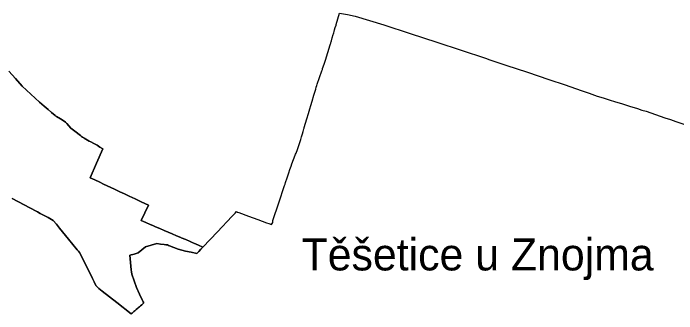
# Model space of a CAD drawing. Extents: x -637420 to -632365, y -1190340 to -1186955.
# Drawn here: x -635803 to -634390, y -1190340 to -1189699 of the extents above; entities that cross this region are included whole.
import ezdxf

# ---------------------------------------------------------------- set-up
doc = ezdxf.new("R2010")
doc.units = 0
for name, color, linetype in [('legenda', 7, 'Continuous'), ('Vrstva 1', 7, 'Continuous'), ('Vrstva 10', 7, 'Continuous'), ('Vrstva 11', 7, 'Continuous')]:
    doc.layers.add(name, color=color, linetype=linetype)

msp = doc.modelspace()

# ---------------------------------------------------------------- linework, layer by layer
at = {"layer": 'Vrstva 1'}
for points in [[(-635491.3, -1190157.8), (-635500.3, -1190153.9), (-635505.9, -1190151.5), (-635511.6, -1190149), (-635521.3, -1190144.8), (-635531, -1190140.6), (-635523.2, -1190124.3), (-635515.3, -1190107.9), (-635523, -1190104.3), (-635530.7, -1190100.7), (-635543.7, -1190094.6), (-635556.8, -1190088.5), (-635566.5, -1190083.9), (-635576.3, -1190079.3), (-635582.2, -1190076.5), (-635588, -1190073.8), (-635595.6, -1190070.3), (-635603.1, -1190066.7), (-635611.2, -1190062.9), (-635619.4, -1190059.1), (-635629.7, -1190054.2), (-635640, -1190049.4), (-635626.4, -1190018.5), (-635612.9, -1189987.6), (-635619, -1189984), (-635625, -1189980.4), (-635631.5, -1189976.8), (-635638, -1189973.2), (-635641.5, -1189971.2), (-635645.1, -1189969.2), (-635648.7, -1189967.2), (-635652.4, -1189965.1), (-635653.4, -1189964.6), (-635654.4, -1189964), (-635656.1, -1189962.7), (-635657.8, -1189961.4), (-635660.4, -1189959.4), (-635663, -1189957.4), (-635669.2, -1189952.6), (-635675.4, -1189947.9), (-635678, -1189945.9), (-635680.6, -1189943.9), (-635685.1, -1189938.7), (-635689.7, -1189933.6), (-635692.2, -1189931.1), (-635694.7, -1189928.6), (-635703.1, -1189923.9), (-635711.5, -1189919.2), (-635712.8, -1189918.1), (-635714.2, -1189916.9), (-635721.7, -1189910.6), (-635729.2, -1189904.2), (-635738, -1189896.8), (-635747.5, -1189888.6), (-635765.9, -1189871.4), (-635784.2, -1189854.1), (-635798.7, -1189838.1), (-635813.2, -1189822.2)], [(-635805.9, -1190093.5), (-635780.4, -1190107.2), (-635755, -1190120.8), (-635753.5, -1190121.6), (-635752, -1190122.4), (-635746.1, -1190125.6), (-635740.2, -1190128.8), (-635729.4, -1190134.6), (-635718.7, -1190140.4), (-635711.7, -1190148.8), (-635704.8, -1190157.3), (-635686, -1190180.2), (-635667.2, -1190203.2), (-635664.7, -1190206.2), (-635662.1, -1190209.3)], [(-635399.4, -1190197.5), (-635409, -1190193.3), (-635418.7, -1190189.1), (-635422.7, -1190187.4), (-635426.7, -1190185.7), (-635436.2, -1190181.6), (-635445.7, -1190177.5), (-635446.7, -1190177.1), (-635455.7, -1190173.2), (-635464.8, -1190169.2), (-635473.5, -1190165.5), (-635482.3, -1190161.7), (-635491.3, -1190157.8)], [(-635525.1, -1190316.4), (-635526.7, -1190313.9), (-635528.2, -1190311.4), (-635534.5, -1190297.6), (-635540.7, -1190283.8), (-635545.7, -1190269.4), (-635550.7, -1190255), (-635551.6, -1190250.5), (-635552.5, -1190245.9), (-635553.2, -1190238.2), (-635553.9, -1190230.4), (-635554.7, -1190222.7), (-635555.4, -1190215), (-635546.2, -1190212.2), (-635537.1, -1190209.4), (-635529.4, -1190203.2), (-635521.7, -1190197), (-635509.8, -1190193.4), (-635497.8, -1190189.9), (-635490.1, -1190190.9), (-635482.3, -1190191.9)], [(-635482.3, -1190191.9), (-635478.5, -1190192.4), (-635474.6, -1190192.9), (-635472.7, -1190193.7), (-635470.8, -1190194.4), (-635461.6, -1190198.2), (-635452.3, -1190201.9), (-635444.4, -1190203.9), (-635436.5, -1190205.9), (-635424.3, -1190208.4), (-635412.1, -1190210.9), (-635410.4, -1190209.1), (-635408.1, -1190206.7), (-635403.7, -1190202.1), (-635399.4, -1190197.5)], [(-635662.1, -1190209.3), (-635648.3, -1190236.8), (-635634.5, -1190264.3), (-635631, -1190271.8), (-635627.4, -1190279.2), (-635620.9, -1190285.4), (-635614.4, -1190291.7), (-635583.2, -1190315.6), (-635552, -1190339.6), (-635550.3, -1190338.1), (-635548.6, -1190336.6), (-635546.7, -1190335), (-635544.8, -1190333.4), (-635541.5, -1190330.6), (-635538.3, -1190327.8), (-635536.4, -1190326.2), (-635534.5, -1190324.5), (-635532.6, -1190322.8), (-635529.9, -1190320.6), (-635528.2, -1190319.1), (-635526.1, -1190317.3), (-635525.1, -1190316.4)]]:
    msp.add_lwpolyline(points, dxfattribs=at)
at = {"layer": 'Vrstva 10'}
for points in [[(-635183.6, -1189942.7), (-635180.7, -1189933.1), (-635177.9, -1189923.6), (-635174.6, -1189912.4), (-635171.7, -1189902.9), (-635169.5, -1189895.5), (-635166.7, -1189885.9), (-635162.9, -1189873.2), (-635159.1, -1189860.5), (-635158, -1189856.7), (-635156.9, -1189853), (-635155.9, -1189850.1), (-635151, -1189835.7), (-635146, -1189821.3), (-635145.5, -1189819.9), (-635145, -1189818.5), (-635144.7, -1189817.5), (-635144.4, -1189816.6), (-635141.2, -1189807.6), (-635138.1, -1189798.6), (-635133.3, -1189782.5), (-635128.5, -1189766.3), (-635127.9, -1189764.3), (-635127.3, -1189762.2), (-635127, -1189761.4), (-635126.4, -1189759.4), (-635125.8, -1189757.4), (-635123.9, -1189750.8), (-635121.9, -1189744.1), (-635121.4, -1189742.4), (-635120.9, -1189740.7), (-635119.9, -1189737.4), (-635118.9, -1189734.1), (-635117.4, -1189729.2), (-635115.9, -1189724.3), (-635115.7, -1189723.4), (-635115.4, -1189722.6), (-635111.9, -1189710.6), (-635108.3, -1189698.7)], [(-635108.3, -1189698.7), (-635091.6, -1189701.7), (-635074.9, -1189704.6), (-635044.6, -1189714), (-635014.4, -1189723.3), (-634957.8, -1189741.9), (-634901.3, -1189760.6), (-634849.6, -1189777.6), (-634797.8, -1189794.7), (-634788.2, -1189797.9), (-634771.1, -1189803.6), (-634754.1, -1189809.2), (-634708.2, -1189824.5), (-634662.4, -1189839.8), (-634628, -1189851.7), (-634593.7, -1189863.5), (-634576.6, -1189869.4), (-634559.6, -1189875.3), (-634546.6, -1189879.3), (-634533.7, -1189883.4), (-634520.7, -1189887.4), (-634507.8, -1189891.5), (-634490.5, -1189896.9), (-634473.3, -1189902.2), (-634464.2, -1189905.1), (-634455.1, -1189907.9), (-634435.2, -1189914.7), (-634415.4, -1189921.5), (-634403.3, -1189925.6), (-634397.5, -1189927.6), (-634391.7, -1189929.6), (-634320.3, -1189953.4)], [(-635813.2, -1189822.2), (-635798.7, -1189838.1), (-635784.2, -1189854.1), (-635765.9, -1189871.4), (-635747.5, -1189888.6), (-635738, -1189896.8), (-635729.2, -1189904.2), (-635721.7, -1189910.6), (-635714.2, -1189916.9), (-635712.8, -1189918.1), (-635711.5, -1189919.2), (-635703.1, -1189923.9), (-635694.7, -1189928.6), (-635692.2, -1189931.1), (-635689.7, -1189933.6), (-635685.1, -1189938.7), (-635680.6, -1189943.9), (-635678, -1189945.9), (-635675.4, -1189947.9), (-635669.2, -1189952.6), (-635663, -1189957.4), (-635660.4, -1189959.4), (-635657.8, -1189961.4), (-635656.1, -1189962.7), (-635654.4, -1189964), (-635653.4, -1189964.6), (-635652.4, -1189965.1), (-635648.7, -1189967.2), (-635645.1, -1189969.2), (-635641.5, -1189971.2), (-635638, -1189973.2), (-635631.5, -1189976.8), (-635625, -1189980.4), (-635619, -1189984), (-635612.9, -1189987.6), (-635626.4, -1190018.5), (-635640, -1190049.4), (-635629.7, -1190054.2), (-635619.4, -1190059.1), (-635611.2, -1190062.9), (-635603.1, -1190066.7), (-635595.6, -1190070.3), (-635588, -1190073.8), (-635582.2, -1190076.5), (-635576.3, -1190079.3), (-635566.5, -1190083.9), (-635556.8, -1190088.5), (-635543.7, -1190094.6), (-635530.7, -1190100.7), (-635523, -1190104.3), (-635515.3, -1190107.9), (-635523.2, -1190124.3), (-635531, -1190140.6), (-635521.3, -1190144.8), (-635511.6, -1190149), (-635505.9, -1190151.5), (-635500.3, -1190153.9), (-635491.3, -1190157.8)], [(-635399.4, -1190197.5), (-635368.7, -1190165), (-635338, -1190132.5), (-635336.2, -1190130.6), (-635334.3, -1190128.6), (-635331.1, -1190125.2), (-635327.9, -1190121.8), (-635325.6, -1190122.7), (-635323.2, -1190123.6), (-635322.8, -1190123.7), (-635302.5, -1190131.2), (-635282.3, -1190138.7), (-635273.3, -1190142), (-635264.2, -1190145.4), (-635258.8, -1190147.4), (-635253.3, -1190149.4), (-635251.8, -1190147.2), (-635250.2, -1190145), (-635250.2, -1190145), (-635250.3, -1190142.8), (-635250.4, -1190140.7), (-635237.9, -1190103.4), (-635225.4, -1190066.2), (-635224.4, -1190063.1), (-635223.3, -1190059.9), (-635219.9, -1190049.5), (-635216.4, -1190039.1), (-635214, -1190031.9), (-635211.6, -1190024.7), (-635209.8, -1190020.1), (-635206.2, -1190010.6), (-635202.6, -1190001.2), (-635201.9, -1189999.3), (-635201.1, -1189997.4), (-635201.1, -1189997.2), (-635201, -1189997), (-635198, -1189989.1), (-635195, -1189981.1), (-635193.1, -1189974.7), (-635191.2, -1189968.3), (-635189.4, -1189962.2), (-635187.6, -1189956.1), (-635185.9, -1189950.7), (-635184.3, -1189945.3), (-635183.9, -1189944), (-635183.6, -1189942.7)], [(-635491.3, -1190157.8), (-635482.3, -1190161.7), (-635473.5, -1190165.5), (-635464.8, -1190169.2), (-635455.7, -1190173.2), (-635446.7, -1190177.1), (-635445.7, -1190177.5), (-635436.2, -1190181.6), (-635426.7, -1190185.7), (-635422.7, -1190187.4), (-635418.7, -1190189.1), (-635409, -1190193.3), (-635399.4, -1190197.5)]]:
    msp.add_lwpolyline(points, dxfattribs=at)
at = {"layer": 'Vrstva 11'}
for points in [[(-635662.1, -1190209.3), (-635664.7, -1190206.2), (-635667.2, -1190203.2), (-635686, -1190180.2), (-635704.8, -1190157.3), (-635711.7, -1190148.8), (-635718.7, -1190140.4), (-635729.4, -1190134.6), (-635740.2, -1190128.8), (-635746.1, -1190125.6), (-635752, -1190122.4), (-635753.5, -1190121.6), (-635755, -1190120.8), (-635780.4, -1190107.2), (-635805.9, -1190093.5)], [(-635482.3, -1190191.9), (-635490.1, -1190190.9), (-635497.8, -1190189.9), (-635509.8, -1190193.4), (-635521.7, -1190197), (-635529.4, -1190203.2), (-635537.1, -1190209.4), (-635546.2, -1190212.2), (-635555.4, -1190215), (-635554.7, -1190222.7), (-635553.9, -1190230.4), (-635553.2, -1190238.2), (-635552.5, -1190245.9), (-635551.6, -1190250.5), (-635550.7, -1190255), (-635545.7, -1190269.4), (-635540.7, -1190283.8), (-635534.5, -1190297.6), (-635528.2, -1190311.4), (-635526.7, -1190313.9), (-635525.1, -1190316.4)], [(-635399.4, -1190197.5), (-635403.7, -1190202.1), (-635408.1, -1190206.7), (-635410.4, -1190209.1), (-635412.1, -1190210.9), (-635424.3, -1190208.4), (-635436.5, -1190205.9), (-635444.4, -1190203.9), (-635452.3, -1190201.9), (-635461.6, -1190198.2), (-635470.8, -1190194.4), (-635472.7, -1190193.7), (-635474.6, -1190192.9), (-635478.5, -1190192.4), (-635482.3, -1190191.9)], [(-635525.1, -1190316.4), (-635526.1, -1190317.3), (-635528.2, -1190319.1), (-635529.9, -1190320.6), (-635532.6, -1190322.8), (-635534.5, -1190324.5), (-635536.4, -1190326.2), (-635538.3, -1190327.8), (-635541.5, -1190330.6), (-635544.8, -1190333.4), (-635546.7, -1190335), (-635548.6, -1190336.6), (-635550.3, -1190338.1), (-635552, -1190339.6), (-635583.2, -1190315.6), (-635614.4, -1190291.7), (-635620.9, -1190285.4), (-635627.4, -1190279.2), (-635631, -1190271.8), (-635634.5, -1190264.3), (-635648.3, -1190236.8), (-635662.1, -1190209.3)]]:
    msp.add_lwpolyline(points, dxfattribs=at)

# ---------------------------------------------------------------- texts
at = {"layer": 'legenda'}
msp.add_text('Těšetice u Znojma', height=68.198, dxfattribs=at).set_placement((-635189.3, -1190247.2))

doc.saveas('drawing.dxf')
